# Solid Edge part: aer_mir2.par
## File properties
Author: Kasutaja
Template: Ansi Inch Part.par
Last saved by: Kasutaja
Revision: 2
Application: Solid Edge
Accuracy: 0,990
Username: Kasutaja
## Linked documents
aer.par
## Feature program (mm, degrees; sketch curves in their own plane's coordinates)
part copy "CopiedPart_1"
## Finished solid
Body 1: solid body, 8 faces, 12 edges, 6 vertices.
  Faces by surface: blend 3, spline 3, plane 2
  Edges by curve: curve on surface 6, intersection 6
Bounding box of the edges (mm; curved faces can reach further): 9.363 x 230.812 x 18.909, from (-4.6814, 0, -9.4545) to (4.6813, 230.8122, 9.4544).
Planar faces by outward normal: +y 1, -y 1
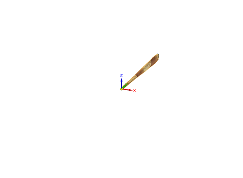
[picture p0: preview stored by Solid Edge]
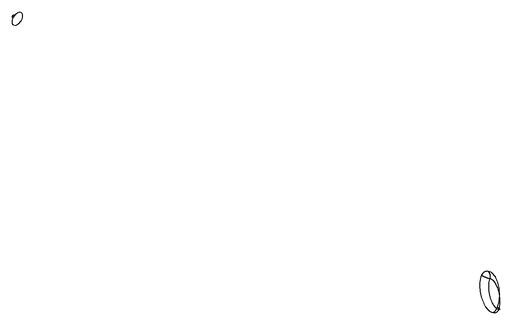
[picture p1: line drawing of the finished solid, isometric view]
